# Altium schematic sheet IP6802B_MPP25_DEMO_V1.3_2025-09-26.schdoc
size 556 x 390 mm
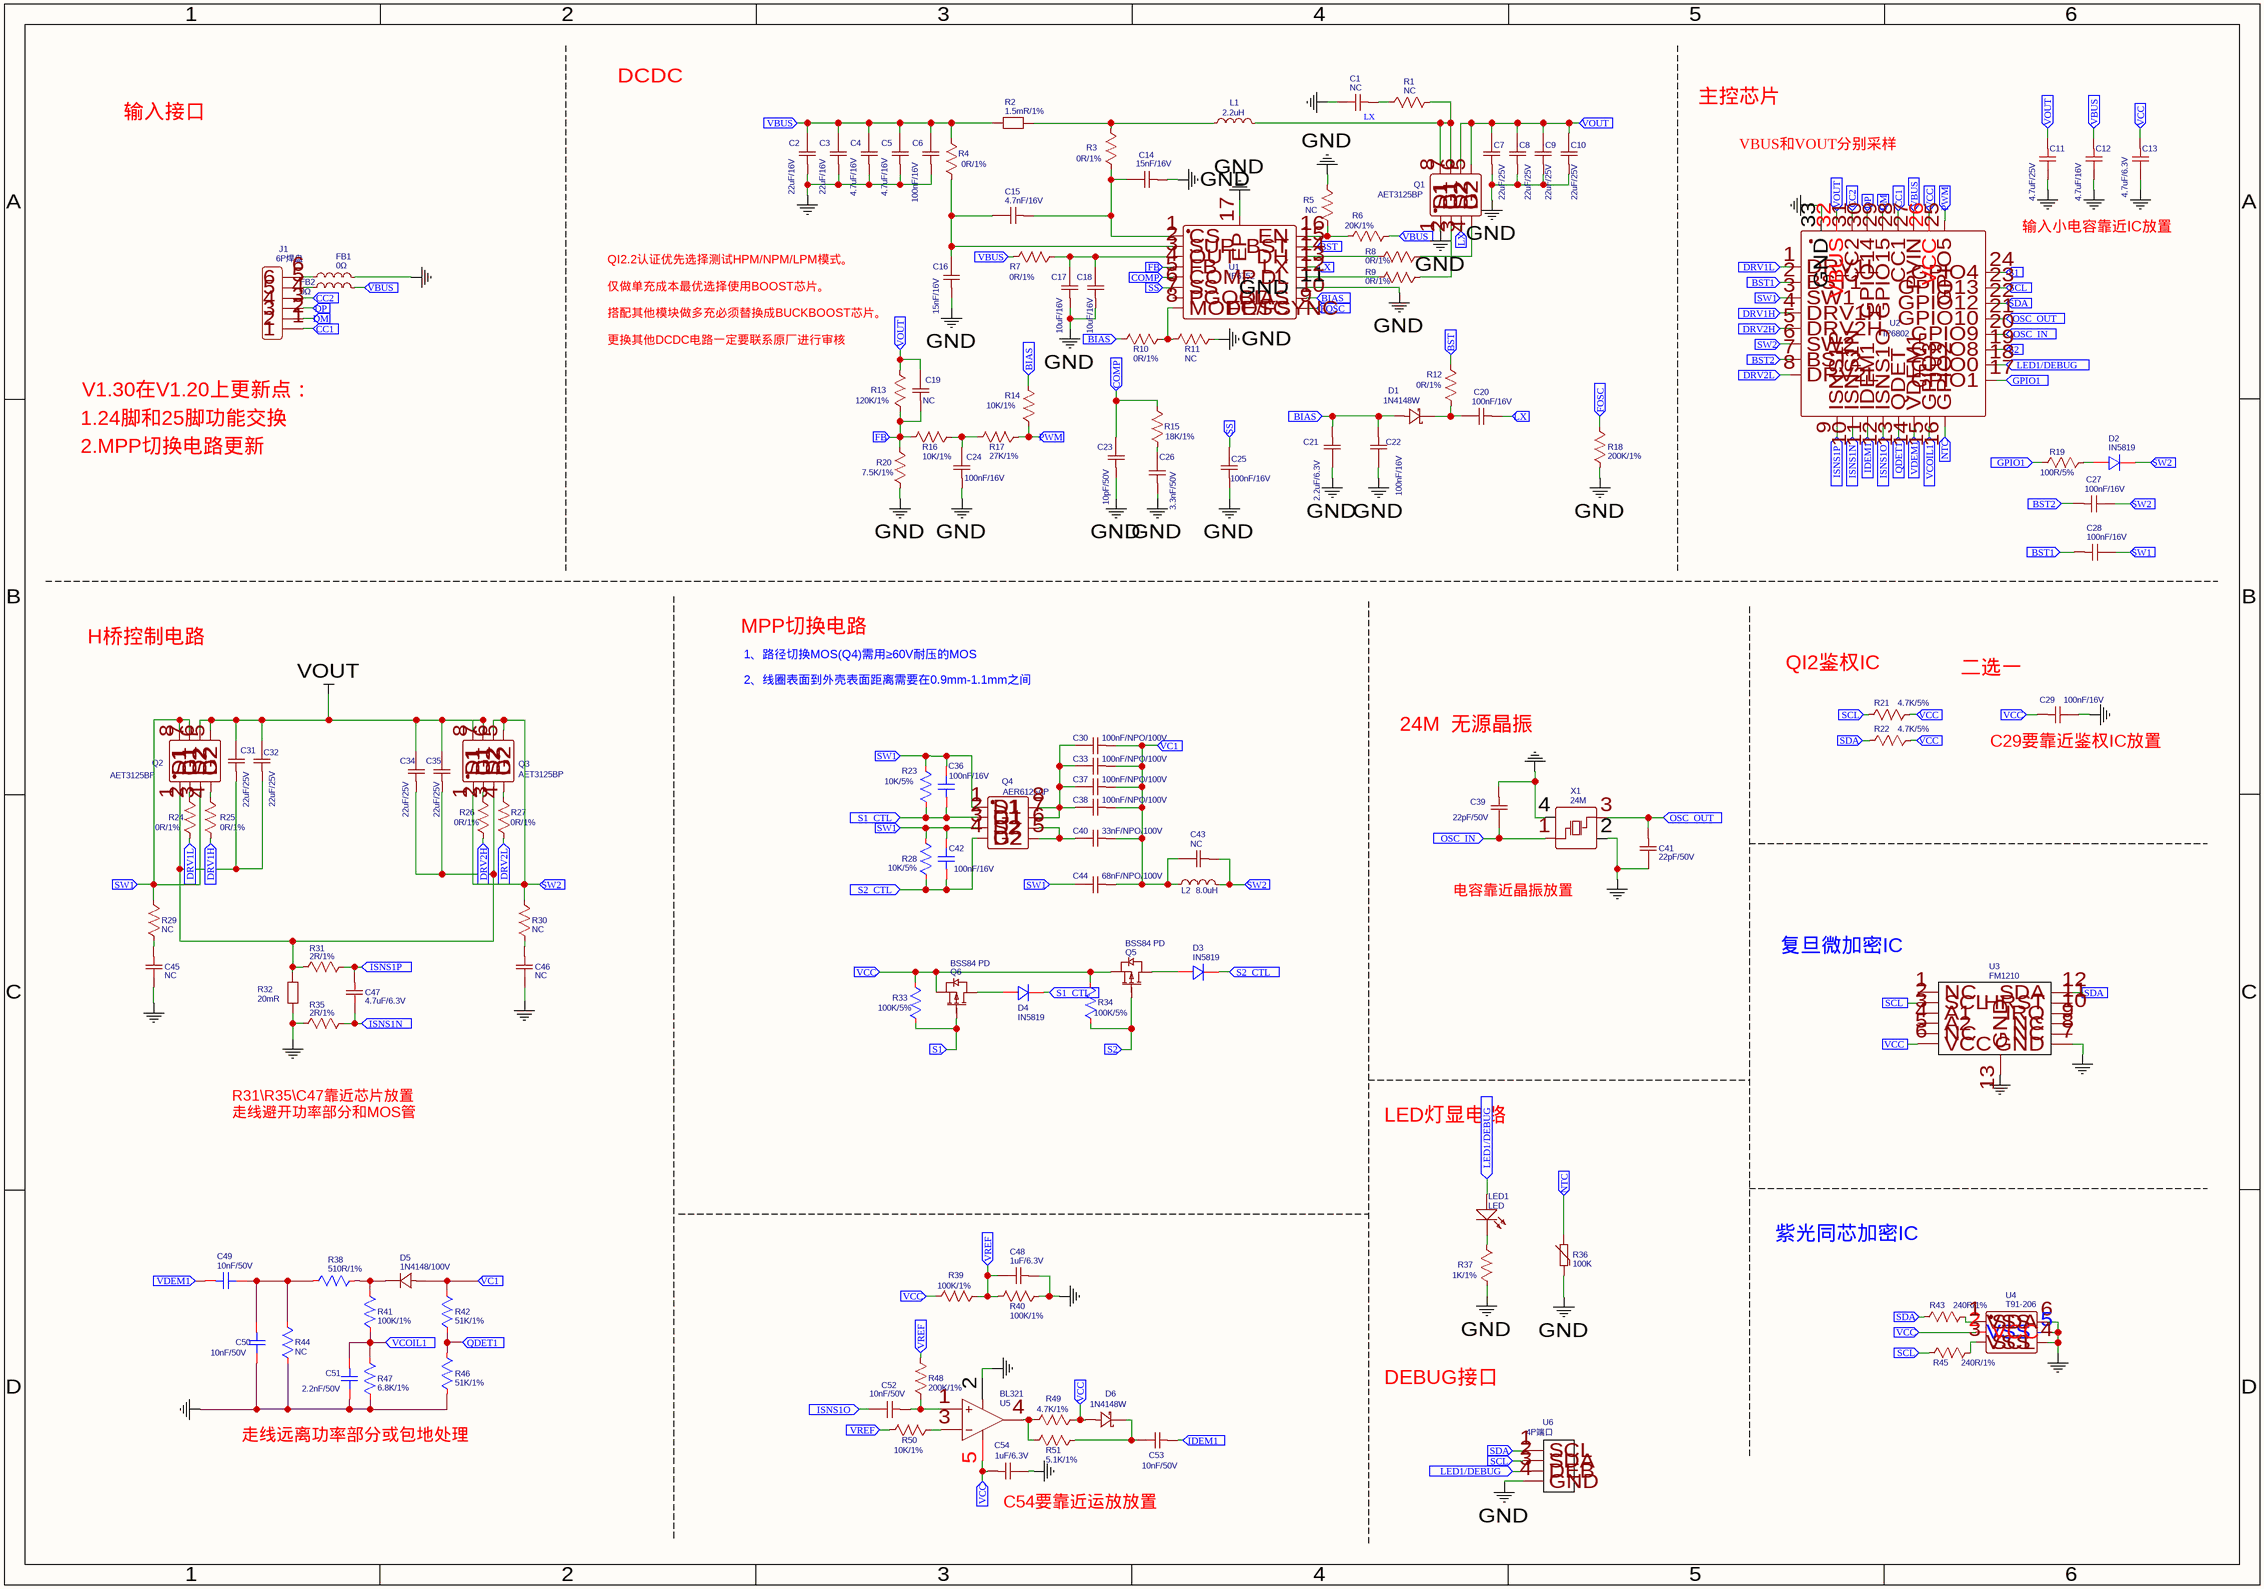
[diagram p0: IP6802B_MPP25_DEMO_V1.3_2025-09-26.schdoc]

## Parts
C1  NC  [C0402]
C2  22uF/16V  [C0805]
C3  22uF/16V  [C0805]
C4  4.7uF/16V  [C0402]
C5  4.7uF/16V  [C0402]
C6  100nF/16V  [C0402]
C7  22uF/25V  [C0805]
C8  22uF/25V  [C0805]
C9  22uF/25V  [C0805]
C10  22uF/25V  [C0805]
C11  4.7uF/25V  [C0402]
C12  4.7uF/16V  [C0402]
C13  4.7uF/6.3V  [C0402]
C14  15nF/16V  [C0402]
C15  4.7nF/16V  [C0402]
C16  15nF/16V  [C0402]
C17  10uF/16V  [C0603]
C18  10uF/16V  [C0603]
C19  NC  [C0402]
C20  100nF/16V  [C0402]
C21  2.2uF/6.3V  [C0402]
C22  100nF/16V  [C0402]
C23  10pF/50V  [C0402]
C24  100nF/16V  [C0402]
C25  100nF/16V  [C0402]
C26  3.3nF/50V  [C0402]
C27  100nF/16V  [C0402]
C28  100nF/16V  [C0402]
C29  100nF/16V  [C0402]
C30  100nF/NPO/100V  [C1206]
C31  22uF/25V  [C0805]
C32  22uF/25V  [C0805]
C33  100nF/NPO/100V  [C1206]
C34  22uF/25V  [C0805]
C35  22uF/25V  [C0805]
C36  100nF/16V  [C0402]
C37  100nF/NPO/100V  [C1206]
C38  100nF/NPO/100V  [C1206]
C39  22pF/50V  [C0402]
C40  33nF/NPO/100V  [C1206]
C41  22pF/50V  [C0402]
C42  100nF/16V  [C0402]
C43  NC  [C0402]
C44  68nF/NPO/100V  [C1206]
C45  NC  [C0402]
C46  NC  [C0402]
C47  4.7uF/6.3V  [C0402]
C48  1uF/6.3V  [C0402]
C49  10nF/50V  [C0402]
C50  10nF/50V  [C0402]
C51  2.2nF/50V  [C0402]
C52  10nF/50V  [C0402]
C53  10nF/50V  [C0402]
C54  1uF/6.3V  [C0402]
D1  1N4148W  [SOD-323_L1.7-W1.3-LS2.6-FD-1]
D2  IN5819  [SOD-323FH_L2.0-W1.3-LS2.7-RD]
D3  IN5819  [SOD-323FH_L2.0-W1.3-LS2.7-RD]
D4  IN5819  [SOD-323FH_L2.0-W1.3-LS2.7-RD]
D5  1N4148/100V  [SOD-323_L1.7-W1.3-LS2.5-FD]
D6  1N4148W  [SOD-323_L1.7-W1.3-LS2.6-FD-1]
FB1  0Ω  [L1206]
FB2  0Ω  [L1206]
J1  6P焊盘  [6P焊盘]
L1  2.2uH  [IND-SMD_L6.0-W6.0]
L2  8.0uH  [IND-SMD_L6.0-W6.0]
LED1  LED  [LED0402-RD-1-2]
Q1  AET3125BP  [PDFN3333-8_L3.1-W3.1-P0.65-LS3.4-BL-EP]
Q2  AET3125BP  [PDFN3333-8_L3.1-W3.1-P0.65-LS3.4-BL-EP]
Q3  AET3125BP  [PDFN3333-8_L3.1-W3.1-P0.65-LS3.4-BL-EP]
Q4  AER6125AP  [PDFN3333-8_L3.1-W3.1-P0.65-LS3.4-BL-EP]
Q5  BSS84 PD  [SOT-23-3_L2.9-W1.3-P0.95-LS2.4-BR-1]
Q6  BSS84 PD  [SOT-23-3_L2.9-W1.3-P0.95-LS2.4-BR-1]
R1  NC  [R0402]
R2  1.5mR/1%  [R1206_1]
R3  0R/1%  [R0402]
R4  0R/1%  [R0402]
R5  NC  [R0402]
R6  20K/1%  [R0402]
R7  0R/1%  [R0402]
R8  0R/1%  [R0402]
R9  0R/1%  [R0402]
R10  0R/1%  [R0402]
R11  NC  [R0402]
R12  0R/1%  [R0402]
R13  120K/1%  [R0402]
R14  10K/1%  [R0402]
R15  18K/1%  [R0402]
R16  10K/1%  [R0402]
R17  27K/1%  [R0402]
R18  200K/1%  [R0402]
R19  100R/5%  [R0402]
R20  7.5K/1%  [R0402]
R21  4.7K/5%  [R0402]
R22  4.7K/5%  [R0402]
R23  10K/5%  [R0402]
R24  0R/1%  [R0402]
R25  0R/1%  [R0402]
R26  0R/1%  [R0402]
R27  0R/1%  [R0402]
R28  10K/5%  [R0402]
R29  NC  [R0402]
R30  NC  [R0402]
R31  2R/1%  [R0402]
R32  20mR  [R1206_1]
R33  100K/5%  [R0402]
R34  100K/5%  [R0402]
R35  2R/1%  [R0402]
R36  100K  [R0402]
R37  1K/1%  [R0402]
R38  510R/1%  [R0402]
R39  100K/1%  [R0402]
R40  100K/1%  [R0402]
R41  100K/1%  [R0402]
R42  51K/1%  [R0402]
R43  240R/1%  [R0402]
R44  NC  [R0402]
R45  240R/1%  [R0402]
R46  51K/1%  [R0402]
R47  6.8K/1%  [R0402]
R48  200K/1%  [R0402]
R49  4.7K/1%  [R0402]
R50  10K/1%  [R0402]
R51  5.1K/1%  [R0402]
U1  IP6752  [TQFN-16_L3.0-W3.0-P0.50-BL-EP1.7]
U2  IP6802  [QFN-32_L5.0-W5.0-P0.50-BL-EP3.4]
U3  FM1210  [FM1230]
U4  T91-206  [DFN6_I2C]
U5  BL321  [SOT-23-5_L2.9-W1.6-P0.95-LS2.8-BR]
U6  4P端口  [4P焊盘]
X1  24M  [CRYSTAL-SMD_4P-L2.5-W2.0-BL]

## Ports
BIAS (in), BST1 (in), BST2 (in), BST (in), CC1 (in), CC2 (in), COMP (in), DM (in), DP (in), DRV1H (in), DRV1L (in), DRV2H (in), DRV2L (in), FB (in), FOSC (in), GPIO1 (in), IDEM1 (in), ISNS1N (in), ISNS1O (in), ISNS1P (in), LED1/DEBUG (in), LX (in), NTC (in), OSC_IN (in), OSC_OUT (in), PWM (in), QDET1 (in), S1 (in), S1_CTL (in), S2 (in), S2_CTL (in), SCL (in), SDA (in), SS (in), SW1 (in), SW2 (in), VBUS (in), VC1 (in), VCC (in), VCOIL1 (in), VDEM1 (in), VOUT (in), VREF (in)

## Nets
GND: C1.1 C2.2 C3.2 C4.2 C5.2 C6.2 C7.2 C8.2 C9.2 C10.2 C11.1 C12.1 C13.1 C14.2 C16.2 C17.2 C18.2 C21.1 C22.1 C23.2 C24.2 C25.2 C26.2 C29.1 C39.2 C41.1 C45.1 C46.1 C48.2 C50.1 C51.1 C54.1 FB1.2 Q1.1(S1) R5.1 R11.2 R18.2 R20.2 R32.1 R35.2 R36.1 R37.1 R40.2 R44.2 R46.1 R47.1 U1.11(GND) U1.17(EP) U2.33(GND) U3.7(GND) U3.13(GND) U4.4(VSS) U4.5(VSS) U4.6(VSS) U5.2(v-) U6.4(GND) X1.2(GND) X1.4(GND)
VOUT: C31.1 C32.1 C34.1 C35.1 Q2.5(D2) Q2.6(D2) Q3.7(D1) Q3.8(D1)
BIAS: C21.2 C22.2 D1.1(A) R10.1 R14.1 U1.10(BIAS) ; port BIAS
BST: R12.1 U1.15(BST) ; port BST
BST1: C28.2 U2.2(BST1) ; port BST1
BST2: C27.2 U2.7(BST2) ; port BST2
CC1: J1.1 U2.28(CC1) ; port CC1
CC2: J1.4 U2.31(CC2) ; port CC2
COMP: C23.1 R15.1 U1.5(COMP) ; port COMP
DM: J1.2 U2.29(GPIO15) ; port DM
DP: J1.3 U2.30(GPIO14) ; port DP
DRV1H: R25.2 U2.4(DRV1H) ; port DRV1H
DRV1L: C28.1 C36.1 C42.1 C44.1 Q2.3(S2) Q2.7(D1) Q2.8(D1) Q4.1(S1) Q4.3(S2) R23.1 R24.2 R28.1 R29.1 U2.1(DRV1L) U2.3(SW1) ; port SW1, port DRV1L
DRV2H: C27.1 C43.2 D2.1(K) L2.2 Q3.1(S1) Q3.5(D2) Q3.6(D2) R26.2 R27.2 R30.1 U2.5(DRV2H) U2.6(SW2) U2.8(DRV2L) ; port DRV2L, port SW2, port DRV2H
FB: C19.2 R13.1 R16.1 R20.1 U1.4(FB) ; port FB
FOSC: R18.1 U1.9(FOSC) ; port FOSC
GPIO1: R19.2 U2.17(GPIO1) ; port GPIO1
IDEM1: C53.2 U2.11(IDEM1) ; port IDEM1
ISNS1N: C47.1 R35.1 U2.10(ISNS1N) ; port ISNS1N
ISNS1O: C52.1 U2.12(ISNS1O) ; port ISNS1O
ISNS1P: C47.2 R31.1 U2.9(ISNS1P) ; port ISNS1P
LED1/DEBUG: LED1.1(A) U2.18(GPIO0) U6.3(DEB) ; port LED1/DEBUG
LX: L1.2 Q1.7(D1) Q1.8(D1) R1.1
LX: C20.2 Q1.3(S2) U1.13(LX) ; port LX  [a separate net that carries the same name]
NTC: R36.2 U2.16(GPIO2) ; port NTC
OSC_IN: C39.1 U2.20(GPIO9) X1.1(OSC1) ; port OSC_IN
OSC_OUT: C41.2 U2.21(GPIO10) X1.3(OSC2) ; port OSC_OUT
PWM: R14.2 R17.2 U2.25(GPIO5) ; port PWM
QDET1: R42.1 R46.2 U2.13(QDET) ; port QDET1
S1: Q6.1(G) R33.2 U2.24(GPIO4) ; port S1
S1_CTL: C36.2 D4.1(K) Q4.2(G1) R23.2 ; port S1_CTL
S2: Q5.1(G) R34.2 U2.19(GPIO8) ; port S2
S2_CTL: C42.2 D3.1(K) Q4.4(G2) R28.2 ; port S2_CTL
SCL: R21.2 R45.2 U2.23(GPIO13) U3.2(SCL) U6.2(SDA) ; port SCL
SDA: R22.2 R43.2 U2.22(GPIO12) U3.12(SDA) U6.1(SCL) ; port SDA
SS: C25.1 U1.6(SS) ; port SS
VBUS: C2.1 C3.1 C4.1 C5.1 C6.1 C12.2 FB2.2 R2.2 R4.1 R6.1 R7.1 U2.27(PVIN) ; port VBUS
VC1: C30.2 C33.2 C37.2 C38.2 C40.2 C43.1 C44.2 D5.1(A) L2.1 R42.2 ; port VC1
VCC: C13.2 C29.2 C54.2 D6.1(A) Q5.2(S) Q6.2(S) R21.1 R22.1 R33.1 R34.1 R39.1 R49.2 U2.26(VCC) U3.6(VCC) U4.2(VCC) U5.5(V+) ; port VCC
VCOIL1: C51.2 R41.1 R47.2 U2.15(GPIO3) ; port VCOIL1
VDEM1: C49.2 U2.14(VDEM1) ; port VDEM1
VOUT: C7.1 C8.1 C9.1 C10.1 C11.2 C19.1 Q1.5(D2) Q1.6(D2) R13.2 U2.32(VBUS) ; port VOUT  [a separate net that carries the same name]
VREF: C48.1 R39.2 R40.1 R48.1 R50.1 ; port VREF
NetC1_2: C1.2 R1.2
NetC14_1: C14.1 C15.2 R3.2 U1.1(CS)
NetC15_1: C15.1 C16.1 R4.2 U1.2(SUP)
NetC17_1: C17.1 C18.1 R7.2 U1.3(OUT)
NetC20_1: C20.1 D1.2(K) R12.2
NetC24_1: C24.1 R16.2 R17.1
NetC26_1: C26.1 R15.2
NetC30_1: C30.1 C33.1 C37.1 C38.1 Q4.7(D1) Q4.8(D1)
NetC31_2: C31.2 C32.2 C34.2 C35.2 Q2.1(S1) Q3.3(S2) R31.2 R32.2
NetC40_1: C40.1 Q4.5(D2) Q4.6(D2)
NetC45_2: C45.2 R29.2
NetC46_2: C46.2 R30.2
NetC49_1: C49.1 C50.2 R38.2 R44.1
NetC52_2: C52.2 R48.2 U5.1(IN+)
NetC53_1: C53.1 D6.2(K) R51.2
NetD2_2: D2.2(A) R19.1
NetD3_2: D3.2(A) Q5.3(D)
NetD4_2: D4.2(A) Q6.3(D)
NetD5_2: D5.2(K) R38.1 R41.2
NetFB1_1: FB1.1 J1.6
NetFB2_1: FB2.1 J1.5
NetL1_1: L1.1 R2.1 R3.1
NetLED1_2: LED1.2(K) R37.2
NetQ1_2: Q1.2(G1) R9.2
NetQ1_4: Q1.4(G2) R8.1
NetQ2_2: Q2.2(G1) R24.1
NetQ2_4: Q2.4(G2) R25.1
NetQ3_2: Q3.2(G1) R26.1
NetQ3_4: Q3.4(G2) R27.1
NetR5_2: R5.2 R6.2 U1.16(EN)
NetR8_2: R8.2 U1.14(DH)
NetR9_1: R9.1 U1.12(DL)
NetR10_2: R10.2 R11.1 U1.8(MODE/FSYNC)
NetR43_1: R43.1 U4.1(SDA)
NetR45_1: R45.1 U4.3(SCL)
NetR49_1: R49.1 R51.1 U5.4(OUT)
NetR50_2: R50.2 U5.3(IN-)

Not connected (* = marked no-connect by the designer): U1 7(PGOOD); U3 1(NC) 3(A1) 4(A2) 5(NC) 8(NC) 9(NC) 10(IRQ) 11(HRST)

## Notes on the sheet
- DCDC
- 主控芯片
- 输入接口
- VBUS和VOUT分别采样
- QI2.2认证优先选择测试HPM/NPM/LPM模式。
  仅做单充成本最优选择使用BOOST芯片。
  搭配其他模块做多充必须替换成BUCKBOOST芯片。
  更换其他DCDC电路一定要联系原厂进行审核
- 输入小电容靠近IC放置
- V1.30在V1.20上更新点：
- 1.24脚和25脚功能交换
- 2.MPP切换电路更新
- H桥控制电路
- MPP切换电路
- 1、路径切换MOS(Q4)需用≥60V耐压的MOS
- QI2鉴权IC
- 二选一
- 2、线圈表面到外壳表面距离需要在0.9mm-1.1mm之间
- 24M  无源晶振
- (near C29) C29要靠近鉴权IC放置
- 电容靠近晶振放置
- 复旦微加密IC
- R31\R35\C47靠近芯片放置
  走线避开功率部分和MOS管
- LED灯显电路
- 紫光同芯加密IC
- DEBUG接口
- 走线远离功率部分或包地处理
- (near C54) C54要靠近运放放置

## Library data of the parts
C1 C19 C43 C45 C46 = NC: nameAlias: Value(F); Contributor: LCEDA_Lib
C2 C3 = 22uF/16V: nameAlias: Value(F); Contributor: LCEDA_Lib
C4 C5 C12 = 4.7uF/16V: nameAlias: Value(F); Contributor: LCEDA_Lib
C6 C20 C22 C24 C25 C27-C29 = 100nF/16V: nameAlias: Value(F); Contributor: LCEDA_Lib
C7-C10 C31 C32 C34 C35 = 22uF/25V: nameAlias: Value(F); Contributor: LCEDA_Lib
C11 = 4.7uF/25V: nameAlias: Value(F); Contributor: LCEDA_Lib
C13 C47 = 4.7uF/6.3V: nameAlias: Value(F); Contributor: LCEDA_Lib
C14 C16 = 15nF/16V: nameAlias: Value(F); Contributor: LCEDA_Lib
C15 = 4.7nF/16V: nameAlias: Value(F); Contributor: LCEDA_Lib
C17 C18 = 10uF/16V: nameAlias: Value(F); Contributor: LCEDA_Lib
C21 = 2.2uF/6.3V: nameAlias: Value(F); Contributor: LCEDA_Lib
C23 = 10pF/50V: nameAlias: Value(F); Contributor: LCEDA_Lib
C26 = 3.3nF/50V: nameAlias: Value(F); Contributor: LCEDA_Lib
C30 C33 C37 C38 = 100nF/NPO/100V: nameAlias: Value(F); Contributor: LCEDA_Lib
C36 C42 = 100nF/16V: nameAlias: Value(F); Contributor: LCEDA_Lib; Package Display: No
C39 C41 = 22pF/50V: nameAlias: Value(F); Contributor: LCEDA_Lib
C40 = 33nF/NPO/100V: nameAlias: Value(F); Contributor: LCEDA_Lib
C44 = 68nF/NPO/100V: nameAlias: Value(F); Contributor: LCEDA_Lib
C48 C54 = 1uF/6.3V: nameAlias: Value(F); Contributor: LCEDA_Lib
C49 C50 = 10nF/50V: nameAlias: Value(F); Contributor: LCEDA_Lib; Package Display: No
C51 = 2.2nF/50V: nameAlias: Value(F); Contributor: LCEDA_Lib; Package Display: No
C52 C53 = 10nF/50V: nameAlias: Value(F); Contributor: LCEDA_Lib
D1 D6 = 1N4148W: Manufacturer: 宏迦橙; Contributor: lcsc
D2-D4 = IN5819: Manufacturer: High Diode; Manufacturer Part: B5819WS; Contributor: LCSC
D5 = 1N4148/100V: Manufacturer: 宏嘉诚; Manufacturer Part: 1N4148WS; Contributor: lcsc
FB1 FB2 = 0Ω: Manufacturer: muRata(村田); Manufacturer Part: BLM31PG601SN1L; nameAlias: Value
L1 = 2.2uH: Manufacturer: SXN(顺翔诺); Manufacturer Part: SMNR4020-2.2UH; nameAlias: Value
L2 = 8.0uH: Manufacturer: COILMX; Manufacturer Part: MPA252012S6R8M; nameAlias: Inductance; Contributor: LCSC
LED1 = LED: Contributor: tycc
Q1-Q3 = AET3125BP: Manufacturer: Vanguard; Manufacturer Part: VS3622DE; Contributor: LCSC
Q4 = AER6125AP: Manufacturer: Vanguard; Manufacturer Part: VS3622DE; Contributor: LCSC
Q5 Q6 = BSS84 PD: Manufacturer: FOSAN(富捷/富信); Contributor: lcsc
R1 R5 R11 R29 R30 = NC: nameAlias: Value(Ω); Contributor: LCEDA_Lib
R2 = 1.5mR/1%: nameAlias: Value(Ω); Contributor: LCEDA_Lib; Package Display: No
R3 R4 R7-R10 R12 R24-R27 = 0R/1%: nameAlias: Value(Ω); Contributor: LCEDA_Lib
R6 = 20K/1%: nameAlias: Value(Ω); Contributor: LCEDA_Lib
R13 = 120K/1%: nameAlias: Value(Ω); Contributor: LCEDA_Lib
R14 R16 R50 = 10K/1%: nameAlias: Value(Ω); Contributor: LCEDA_Lib
R15 = 18K/1%: nameAlias: Value(Ω); Contributor: LCEDA_Lib
R17 = 27K/1%: nameAlias: Value(Ω); Contributor: LCEDA_Lib
R18 R48 = 200K/1%: nameAlias: Value(Ω); Contributor: LCEDA_Lib
R19 = 100R/5%: nameAlias: Value(Ω); Contributor: LCEDA_Lib
R20 = 7.5K/1%: nameAlias: Value(Ω); Contributor: LCEDA_Lib
R21 R22 = 4.7K/5%: nameAlias: Value(Ω); Contributor: LCEDA_Lib
R23 R28 = 10K/5%: nameAlias: Value(Ω); Contributor: LCEDA_Lib; Package Display: No
R31 R35 = 2R/1%: nameAlias: Value(Ω); Contributor: LCEDA_Lib
R32 = 20mR: nameAlias: Value(Ω); Contributor: LCEDA_Lib; Package Display: No
R33 R34 = 100K/5%: nameAlias: Value(Ω); Contributor: LCEDA_Lib; Package Display: No
R36 = 100K: Manufacturer: MuRata; Manufacturer Part: NCP15WF104F03RC; nameAlias: Value
R37 = 1K/1%: nameAlias: Value(Ω); Contributor: LCEDA_Lib
R38 = 510R/1%: nameAlias: Value(Ω); Contributor: LCEDA_Lib; Package Display: No
R39 R40 = 100K/1%: nameAlias: Value(Ω); Contributor: LCEDA_Lib
R41 = 100K/1%: nameAlias: Value(Ω); Contributor: LCEDA_Lib; Package Display: No
R42 R46 = 51K/1%: nameAlias: Value(Ω); Contributor: LCEDA_Lib; Package Display: No
R43 R45 = 240R/1%: nameAlias: Value(Ω); Contributor: LCEDA_Lib
R44 = NC: nameAlias: Value(Ω); Contributor: LCEDA_Lib; Package Display: No
R47 = 6.8K/1%: nameAlias: Value(Ω); Contributor: LCEDA_Lib; Package Display: No
R49 = 4.7K/1%: nameAlias: Value(Ω); Contributor: LCEDA_Lib
R51 = 5.1K/1%: nameAlias: Value(Ω); Contributor: LCEDA_Lib
U1 = IP6752: Manufacturer: ADI(亚德诺)/MAXIM(美信); Manufacturer Part: MAX25201ATED/VY+; Contributor: lcsc
U2 = IP6802: Contributor: zhengkehuan
U3 = FM1210: Contributor: zhengkehuan
U4 = T91-206: Contributor: bigfacecat
U5 = BL321: Manufacturer: BL(上海贝岭); Contributor: LCSC
U6 = 4P端口: Contributor: dianzihobbyist
X1 = 24M: Manufacturer: TAE(雅晶鑫); Manufacturer Part: TAXM12M4RLBDDT2T; nameAlias: Frequency; Contributor: LCSC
